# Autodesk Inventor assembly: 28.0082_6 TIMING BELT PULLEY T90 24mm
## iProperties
Created: 2007-04
Part Number: 28.0082_6 TIMING BELT PULLEY T90 24mm
Document SubType Name: Assembly
Designer: Andy Moles
Author: Andy Moles
